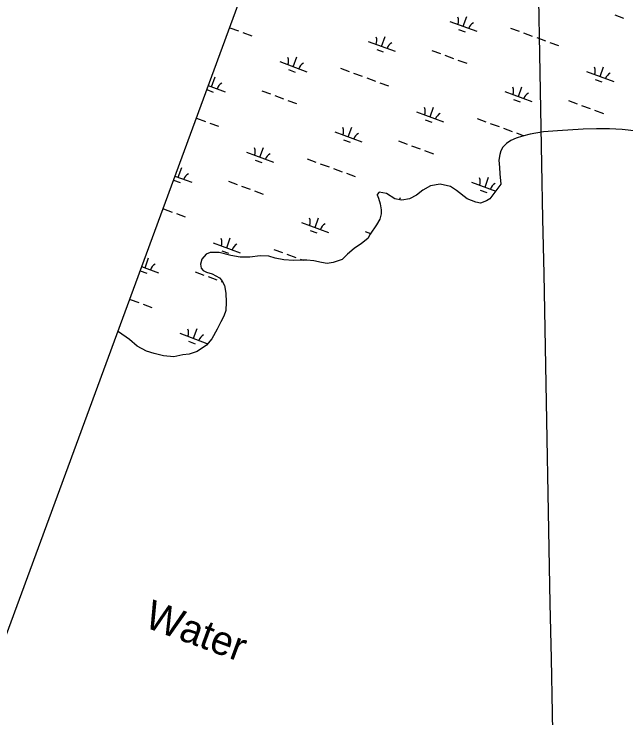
# Model space of a CAD drawing. Extents: x 3972907 to 3994831, y 172639 to 190852.
# Drawn here: x 3977932 to 3978986, y 186115 to 187328 of the extents above; entities that cross this region are included whole.
import ezdxf

# ---------------------------------------------------------------- set-up
doc = ezdxf.new("R2010")
doc.units = 0
for name, color, linetype in [('V-GRID-FRAM', 7, 'Continuous'), ('V-GRID-MAJR', 7, 'Continuous'), ('V-RIVR-IDEN', 7, 'Continuous'), ('V-WETL-SWMP', 7, 'Continuous')]:
    doc.layers.add(name, color=color, linetype=linetype)

msp = doc.modelspace()

# ---------------------------------------------------------------- linework, layer by layer
at = {"layer": 'V-GRID-FRAM'}
msp.add_lwpolyline([(3976065.4, 181215.5), (3978987, 189164.4), (3993292.9, 183906.2), (3990371.3, 175957.4), (3976065.4, 181215.5)], dxfattribs=at)
at = {"layer": 'V-GRID-MAJR'}
msp.add_spline([(3978982.9, 179660), (3978930.1, 182429.9), (3978814.7, 188489.8), (3978791.3, 189715.7)], degree=3, dxfattribs=at)
at = {"layer": 'V-WETL-SWMP'}
for p, q in [((3978706.3, 187307), (3978712.6, 187323.9)), ((3978967.4, 187326.7), (3978982.5, 187321.2)), ((3978682.9, 187315.6), (3978729.8, 187298.4)), ((3978304.2, 187304.6), (3978319.2, 187299.1)), ((3978326.7, 187296.3), (3978341.8, 187290.8)), ((3978698, 187301.8), (3978709.3, 187297.7)), ((3978787.6, 187304.1), (3978802.7, 187298.6)), ((3978810.2, 187295.8), (3978825.2, 187290.3)), ((3978542.1, 187281.1), (3978589, 187263.9)), ((3978565.6, 187272.5), (3978571.8, 187289.4)), ((3978832.7, 187287.6), (3978847.7, 187282)), ((3978855.2, 187279.3), (3978870.2, 187273.8)), ((3978557.3, 187267.3), (3978568.5, 187263.2)), ((3978652, 187265.5), (3978667, 187259.9)), ((3978674.5, 187257.2), (3978689.5, 187251.7)), ((3978389.9, 187246.1), (3978436.9, 187228.8)), ((3978413.4, 187237.4), (3978419.6, 187254.3)), ((3978697, 187248.9), (3978712.1, 187243.4)), ((3978405.1, 187232.3), (3978416.4, 187228.1)), ((3978494.7, 187234.6), (3978509.7, 187229.1)), ((3978941.9, 187220.4), (3978948.1, 187237.3)), ((3978272.6, 187202.9), (3978278.8, 187219.8)), ((3978517.2, 187226.3), (3978532.3, 187220.8)), ((3978918.4, 187229), (3978965.4, 187211.8)), ((3978539.8, 187218), (3978554.8, 187212.5)), ((3978562.3, 187209.7), (3978577.3, 187204.2)), ((3978933.6, 187215.2), (3978944.9, 187211.1)), ((3978264.3, 187197.8), (3978275.6, 187193.6)), ((3978266.9, 187205.1), (3978296.1, 187194.3)), ((3978359, 187195.9), (3978374.1, 187190.4)), ((3978801.1, 187185.9), (3978807.3, 187202.8)), ((3978381.6, 187187.6), (3978396.6, 187182.1)), ((3978777.7, 187194.5), (3978824.6, 187177.3)), ((3978404.1, 187179.4), (3978419.1, 187173.8)), ((3978792.8, 187180.7), (3978804.1, 187176.6)), ((3978887.5, 187178.9), (3978902.5, 187173.4)), ((3978625.5, 187159.5), (3978672.4, 187142.2)), ((3978649, 187150.9), (3978655.2, 187167.7)), ((3978910.1, 187170.6), (3978925.1, 187165.1)), ((3978932.6, 187162.3), (3978947.6, 187156.8)), ((3978246.8, 187148.5), (3978261.9, 187142.9)), ((3978730.3, 187148), (3978745.3, 187142.5)), ((3978269.4, 187140.2), (3978284.4, 187134.7)), ((3978640.7, 187145.7), (3978651.9, 187141.5)), ((3978752.8, 187139.7), (3978767.8, 187134.2)), ((3978484.7, 187125), (3978531.6, 187107.7)), ((3978508.2, 187116.4), (3978514.4, 187133.3)), ((3978775.3, 187131.4), (3978790.3, 187125.9)), ((3978797.8, 187123.2), (3978810.8, 187118.4)), ((3978844.6, 187125.3), (3978821.3, 187121)), ((3978868.7, 187127.1), (3978844.6, 187125.3)), ((3978912.8, 187129.5), (3978868.7, 187127.1)), ((3978936, 187130.1), (3978912.8, 187129.5)), ((3978958, 187130.3), (3978936, 187130.1)), ((3978980, 187129.2), (3978958, 187130.3)), ((3979005.3, 187126.5), (3978980, 187129.2)), ((3978499.9, 187111.2), (3978511.2, 187107.1)), ((3978797.6, 187114.2), (3978788.4, 187110.1)), ((3978808.4, 187117.8), (3978797.6, 187114.2)), ((3978821.3, 187121), (3978808.4, 187117.8)), ((3978594.6, 187109.3), (3978609.6, 187103.8)), ((3978617.1, 187101.1), (3978632.1, 187095.5)), ((3978774.2, 187098.7), (3978770.8, 187092.1)), ((3978780.9, 187105.2), (3978774.2, 187098.7)), ((3978788.4, 187110.1), (3978780.9, 187105.2)), ((3978332.6, 187089.9), (3978379.5, 187072.7)), ((3978356, 187081.3), (3978362.2, 187098.2)), ((3978639.7, 187092.8), (3978654.7, 187087.3)), ((3978769, 187086.3), (3978767.3, 187076.3)), ((3978770.8, 187092.1), (3978769, 187086.3)), ((3978347.7, 187076.1), (3978359, 187072)), ((3978437.3, 187078.5), (3978452.3, 187072.9)), ((3978767.3, 187076.3), (3978768.4, 187063.4)), ((3978215.3, 187046.8), (3978221.5, 187063.7)), ((3978459.9, 187070.2), (3978474.9, 187064.7)), ((3978768.4, 187063.4), (3978769.5, 187052.6)), ((3978482.4, 187061.9), (3978497.4, 187056.4)), ((3978504.9, 187053.6), (3978519.9, 187048.1)), ((3978769.5, 187052.6), (3978771, 187034.8)), ((3978207, 187041.6), (3978218.2, 187037.5)), ((3978209.5, 187048.9), (3978238.7, 187038.2)), ((3978301.7, 187039.8), (3978316.7, 187034.3)), ((3978720.3, 187038.4), (3978762.1, 187023)), ((3978743.7, 187029.8), (3978749.9, 187046.7)), ((3978324.2, 187031.5), (3978339.2, 187026)), ((3978650, 187032.2), (3978636.4, 187024.3)), ((3978666.6, 187034.9), (3978650, 187032.2)), ((3978684.5, 187031), (3978666.6, 187034.9)), ((3978694.7, 187024.1), (3978684.5, 187031)), ((3978771, 187034.8), (3978752, 187009.6)), ((3978346.7, 187023.2), (3978361.7, 187017.7)), ((3978561.6, 187021.2), (3978558.1, 187016.9)), ((3978558.1, 187016.9), (3978558.1, 187016.3)), ((3978558.1, 187016.3), (3978560, 187011)), ((3978574.1, 187019), (3978561.6, 187021.2)), ((3978588.6, 187009.7), (3978574.1, 187019)), ((3978625.9, 187015.8), (3978613.5, 187009.6)), ((3978636.4, 187024.3), (3978625.9, 187015.8)), ((3978712.8, 187009.6), (3978694.7, 187024.1)), ((3978735.4, 187024.6), (3978746.7, 187020.5)), ((3978560, 187011), (3978563.1, 187001)), ((3978600.5, 187007), (3978588.6, 187009.7)), ((3978596.4, 187007.9), (3978597.8, 187011.6)), ((3978613.5, 187009.6), (3978600.5, 187007)), ((3978727.7, 187003.9), (3978712.8, 187009.6)), ((3978736.1, 187002.2), (3978727.7, 187003.9)), ((3978746.1, 187006), (3978736.1, 187002.2)), ((3978752, 187009.6), (3978746.1, 187006)), ((3978189.5, 186992.3), (3978204.5, 186986.8)), ((3978563.1, 187001), (3978564.5, 186990.9)), ((3978564.5, 186990.9), (3978564.6, 186983.8)), ((3978212, 186984.1), (3978227, 186978.5)), ((3978450.8, 186960.2), (3978457, 186977.1)), ((3978564.6, 186983.8), (3978562.4, 186974.8)), ((3978427.3, 186968.9), (3978474.3, 186951.6)), ((3978562.4, 186974.8), (3978556.7, 186964.6)), ((3978442.5, 186955.1), (3978453.8, 186950.9)), ((3978537.2, 186953.2), (3978546.6, 186949.8)), ((3978556.7, 186964.6), (3978545.6, 186948.4)), ((3978298.6, 186925.2), (3978304.9, 186942.1)), ((3978541.6, 186941.2), (3978531.1, 186932.7)), ((3978545.6, 186948.4), (3978541.6, 186941.2)), ((3978275.2, 186933.8), (3978322.1, 186916.6)), ((3978531.1, 186932.7), (3978518.1, 186924.1)), ((3978270.4, 186916.8), (3978263.3, 186914.3)), ((3978285.8, 186917.1), (3978270.4, 186916.8)), ((3978305.5, 186912.1), (3978285.8, 186917.1)), ((3978290.3, 186920), (3978301.6, 186915.9)), ((3978379.9, 186922.3), (3978395, 186916.8)), ((3978518.1, 186924.1), (3978507, 186914.4)), ((3978157.9, 186890.7), (3978164.1, 186907.6)), ((3978255.7, 186905.8), (3978253.5, 186896.9)), ((3978263.3, 186914.3), (3978255.7, 186905.8)), ((3978321.7, 186908.8), (3978305.5, 186912.1)), ((3978338.3, 186909.1), (3978321.7, 186908.8)), ((3978356.1, 186911.2), (3978338.3, 186909.1)), ((3978371, 186910.8), (3978356.1, 186911.2)), ((3978382.3, 186907.5), (3978371, 186910.8)), ((3978397.2, 186904.2), (3978382.3, 186907.5)), ((3978402.5, 186914), (3978417.5, 186908.5)), ((3978425, 186905.8), (3978430.1, 186903.9)), ((3978497.7, 186904.7), (3978482.3, 186899.7)), ((3978507, 186914.4), (3978497.7, 186904.7)), ((3978152.1, 186892.8), (3978181.3, 186882.1)), ((3978253.5, 186896.9), (3978254.8, 186889.8)), ((3978413.9, 186903.3), (3978397.2, 186904.2)), ((3978425.8, 186904.1), (3978413.9, 186903.3)), ((3978436.5, 186903.7), (3978425.8, 186904.1)), ((3978449, 186902.7), (3978436.5, 186903.7)), ((3978462.1, 186899.9), (3978449, 186902.7)), ((3978471.6, 186898.3), (3978462.1, 186899.9)), ((3978482.3, 186899.7), (3978471.6, 186898.3)), ((3978149.6, 186885.5), (3978160.8, 186881.4)), ((3978244.3, 186883.7), (3978259.3, 186878.1)), ((3978254.8, 186889.8), (3978257.9, 186886.2)), ((3978257.9, 186886.2), (3978263.8, 186883.4)), ((3978263.8, 186883.4), (3978273.4, 186880)), ((3978273.4, 186880), (3978286, 186873.1)), ((3978266.8, 186875.4), (3978281.8, 186869.9)), ((3978286, 186873.1), (3978290.3, 186869)), ((3978290.3, 186869), (3978294.6, 186860.1)), ((3978289.3, 186867.1), (3978291.6, 186866.3)), ((3978294.6, 186860.1), (3978297.2, 186847.1)), ((3978297.2, 186847.1), (3978298, 186831.7)), ((3978132.1, 186836.2), (3978147.1, 186830.7)), ((3978298, 186831.7), (3978297.1, 186816.8)), ((3978154.6, 186827.9), (3978169.6, 186822.4)), ((3978293.7, 186807.2), (3978288.5, 186797.6)), ((3978297.1, 186816.8), (3978293.7, 186807.2)), ((3978288.5, 186797.6), (3978282.2, 186785)), ((3978241.3, 186769.1), (3978247.5, 186785.9)), ((3978282.2, 186785), (3978273, 186768.2)), ((3978112.3, 186780.3), (3978111, 186780.8)), ((3978131, 186766.9), (3978112.3, 186780.3)), ((3978217.8, 186777.7), (3978264.7, 186760.4)), ((3978144.2, 186755.3), (3978131, 186766.9)), ((3978233, 186763.9), (3978244.2, 186759.7)), ((3978273, 186768.2), (3978263.7, 186757.4)), ((3978160.4, 186747.2), (3978144.2, 186755.3)), ((3978173.6, 186742.7), (3978160.4, 186747.2)), ((3978263.7, 186757.4), (3978247.8, 186746.4)), ((3978189.7, 186738.8), (3978173.6, 186742.7)), ((3978207.6, 186737.4), (3978189.7, 186738.8)), ((3978223, 186740.6), (3978207.6, 186737.4)), ((3978234.2, 186742), (3978223, 186740.6)), ((3978242.5, 186744.5), (3978234.2, 186742)), ((3978247.8, 186746.4), (3978242.5, 186744.5))]:
    msp.add_line(p, q, dxfattribs=at)
for centre, start, end in [((3978680.5, 187316.7), 339.0473, 20.5909), ((3978732.4, 187297.7), 119.0473, 160.5909), ((3978539.7, 187282.2), 339.0473, 20.5909), ((3978591.6, 187263.2), 119.0473, 160.5909), ((3978387.6, 187247.2), 339.0473, 20.5909), ((3978439.4, 187228.1), 119.0473, 160.5909), ((3978916, 187230.2), 339.0473, 20.5909), ((3978967.9, 187211.1), 119.0473, 160.5909), ((3978298.6, 187193.6), 119.0473, 160.5909), ((3978775.3, 187195.7), 339.0473, 20.5909), ((3978827.1, 187176.6), 119.0473, 160.5909), ((3978623.1, 187160.6), 339.0473, 20.5909), ((3978675, 187141.5), 119.0473, 160.5909), ((3978482.3, 187126.1), 339.0473, 20.5909), ((3978534.2, 187107.1), 119.0473, 160.5909), ((3978330.2, 187091.1), 339.0473, 20.5909), ((3978382, 187072), 119.0473, 160.5909), ((3978241.3, 187037.5), 119.0473, 160.5909), ((3978717.9, 187039.5), 339.0473, 20.5909), ((3978769.7, 187020.5), 119.0473, 160.5909), ((3978425, 186970), 339.0473, 20.5909), ((3978476.8, 186950.9), 119.0473, 160.5909), ((3978272.8, 186934.9), 339.0473, 20.5909), ((3978324.7, 186915.9), 119.0473, 160.5909), ((3978183.9, 186881.4), 119.0473, 160.5909), ((3978215.4, 186778.8), 339.0473, 20.5909), ((3978267.3, 186759.7), 119.0473, 160.5909)]:
    msp.add_arc(centre, 17.6, start, end, dxfattribs=at)

# ---------------------------------------------------------------- texts
at = {"layer": 'V-RIVR-IDEN'}
msp.add_text('Water', height=50, rotation=339.8191, dxfattribs=at).set_placement((3978154.3, 186272.2))

doc.saveas('drawing.dxf')
